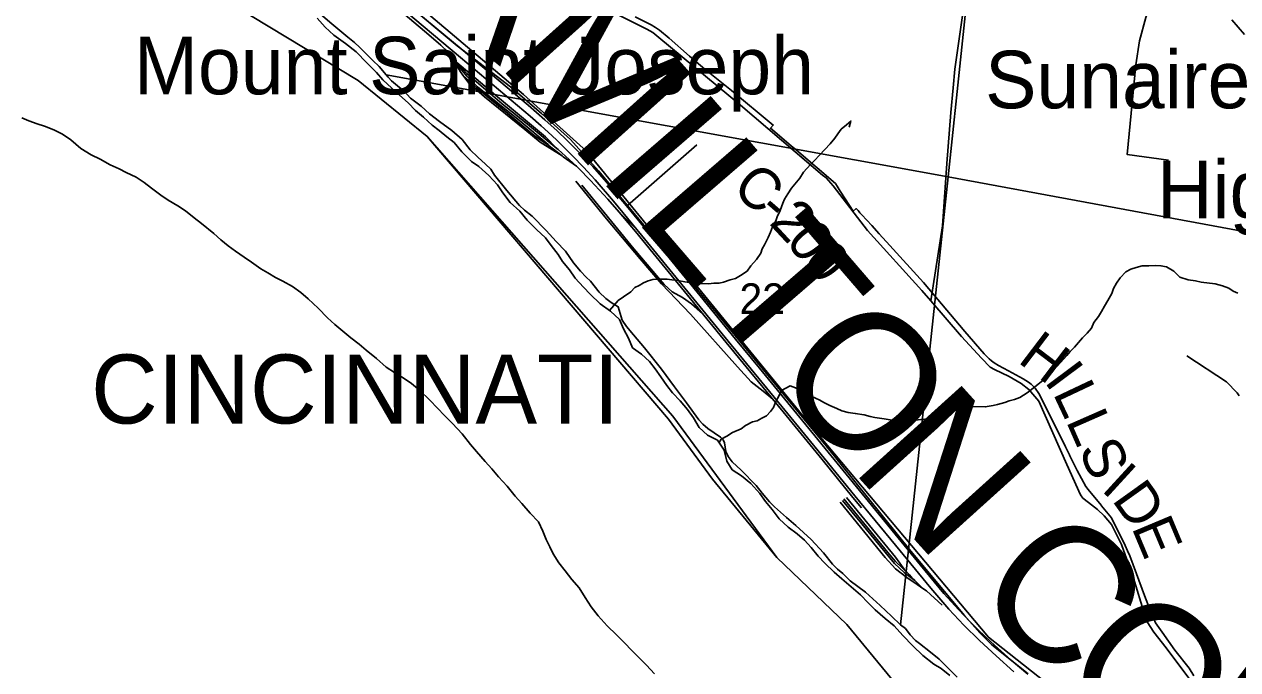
# Model space of a CAD drawing. Extents: x 0 to 43.4, y -8.1 to 22.
# Drawn here: x 5.251 to 6.917, y 14.72 to 15.605 of the extents above; entities that cross this region are included whole.
import ezdxf

# ---------------------------------------------------------------- set-up
doc = ezdxf.new("R2010")
doc.units = 0
for name, color, linetype in [('GM_X_City_Street', 7, 'Continuous'), ('GM_X_Corporation', 7, 'Continuous'), ('GM_X_Corporation_Text', 7, 'Continuous'), ('GM_X_County_Road', 7, 'Continuous'), ('GM_X_County_Road_Text', 7, 'Continuous'), ('GM_X_County_Text', 7, 'Continuous'), ('GM_X_Major_River', 7, 'Continuous'), ('GM_X_Minor_River', 7, 'Continuous'), ('GM_X_Rail_Line', 7, 'Continuous'), ('GM_X_Section_Text', 7, 'Continuous'), ('GM_X_Township_Road', 7, 'Continuous'), ('GM_X_Unincorporated_Text', 7, 'Continuous'), ('GM_X_US_Route', 7, 'Continuous')]:
    doc.layers.add(name, color=color, linetype=linetype)

msp = doc.modelspace()

# ---------------------------------------------------------------- linework, layer by layer
at = {"layer": 'GM_X_City_Street'}
msp.add_line((6.0794, 15.3567), (6.1746, 15.4398), dxfattribs=at)
at = {"layer": 'GM_X_Corporation'}
for points in [[(6.6267, 16.4119), (6.5194, 15.3962), (5.7481, 15.5362), (5.7385, 15.5474), (5.73, 15.5559), (5.7193, 15.566), (5.7119, 15.5734), (5.7045, 15.5804), (5.6956, 15.5878), (5.6844, 15.5968), (5.6733, 15.6058), (5.6644, 15.6136), (5.6543, 15.6226), (5.6473, 15.6288), (5.6384, 15.6362), (5.6358, 15.6382), (5.7092, 16.4607)], [(7.6501, 16.228), (7.5438, 15.2065), (6.5194, 15.3962), (6.6267, 16.4119)], [(6.5194, 15.3962), (6.4541, 14.7814), (6.4415, 14.7931), (6.426, 14.8079), (6.4059, 14.8262), (6.3851, 14.8418), (6.3751, 14.8519), (6.3677, 14.8578), (6.3607, 14.8644), (6.3482, 14.8802), (6.3316, 14.8984), (6.3104, 14.9175), (6.2974, 14.9284), (6.2811, 14.9432), (6.2741, 14.9502), (6.2641, 14.9618), (6.2561, 14.9726), (6.2354, 14.9936), (6.2231, 15.0049), (6.2176, 15.0122), (6.2144, 15.0191), (6.2124, 15.0309), (6.2106, 15.0351), (6.2069, 15.0386), (6.1894, 15.0508), (6.1827, 15.0566), (6.1772, 15.0624), (6.1603, 15.086), (6.1438, 15.108), (6.1258, 15.1319), (6.1027, 15.1612), (6.0876, 15.1794), (6.078, 15.1906), (6.0722, 15.1995), (6.0665, 15.2178), (6.0568, 15.2237), (6.0498, 15.2292), (6.0405, 15.2377), (6.0284, 15.2528), (6.0224, 15.2583), (6.0147, 15.2664), (6.0051, 15.278), (5.9941, 15.2938), (5.9812, 15.3074), (5.9679, 15.3225), (5.9483, 15.3419), (5.9379, 15.3501), (5.9309, 15.3567), (5.9136, 15.3772), (5.897, 15.3984), (5.8916, 15.4065), (5.8845, 15.4135), (5.8738, 15.4229), (5.8634, 15.433), (5.8524, 15.4473), (5.8383, 15.4594), (5.8215, 15.4719), (5.8074, 15.4825), (5.7959, 15.493), (5.7926, 15.4957), (5.7814, 15.5039), (5.7718, 15.5144), (5.7666, 15.5187), (5.7555, 15.528), (5.7507, 15.5327), (5.7481, 15.5362)]]:
    msp.add_lwpolyline(points, close=True, dxfattribs=at)
for points in [[(4.2564, 15.9373), (4.3533, 15.9108), (4.4487, 15.8964), (4.6416, 15.8531), (4.7366, 15.8474), (5.0291, 15.858), (5.1241, 15.8235), (5.4143, 15.7071), (5.7095, 15.5281), (5.8045, 15.4515), (6.1414, 15.0677), (6.2843, 14.8736), (6.3804, 14.7818), (6.459, 14.6859)], [(4.2564, 15.9373), (4.3533, 15.9108), (4.4487, 15.8964), (4.6416, 15.8531), (4.7366, 15.8474), (5.0291, 15.858), (5.1241, 15.8235), (5.4143, 15.7071), (5.7095, 15.5281), (5.8045, 15.4515), (6.1354, 15.0635), (6.1959, 14.9813), (6.2842, 14.8736), (6.3804, 14.7818), (6.459, 14.6859)], [(4.2564, 15.9373), (4.3533, 15.9108), (4.4487, 15.8964), (4.6416, 15.8531), (4.7366, 15.8474), (5.0291, 15.858), (5.1241, 15.8235), (5.4143, 15.7071), (5.7095, 15.5281), (5.8045, 15.4515), (6.1414, 15.0677), (6.2843, 14.8736), (6.3804, 14.7818), (6.459, 14.6859)], [(6.8566, 14.7114), (6.8502, 14.7219), (6.8308, 14.7465), (6.8133, 14.7711), (6.8111, 14.7742), (6.8041, 14.784), (6.7996, 14.795), (6.7955, 14.8052), (6.7903, 14.818), (6.769, 14.876), (6.7657, 14.8828), (6.7622, 14.8899), (6.7437, 14.928), (6.7299, 14.9447), (6.7294, 14.9453), (6.7115, 14.9671), (6.7084, 14.9709), (6.6966, 14.993), (6.691, 15.0041), (6.6865, 15.0132), (6.686, 15.0143), (6.6804, 15.0253), (6.6471, 15.0929), (6.6439, 15.0989), (6.639, 15.1058), (6.6366, 15.1084), (6.6334, 15.1114), (6.6297, 15.1142), (6.6222, 15.1186), (6.6021, 15.1297), (6.5887, 15.1371), (6.5828, 15.1407), (6.5788, 15.1435), (6.5757, 15.1461), (6.5687, 15.1529), (6.5424, 15.184), (6.4856, 15.2508), (6.4394, 15.3018), (6.4246, 15.318), (6.4145, 15.3291), (6.401, 15.344), (6.3997, 15.3454), (6.3984, 15.3468), (6.3971, 15.3482), (6.3958, 15.3496), (6.3945, 15.3511), (6.3933, 15.3524), (6.389, 15.3487), (6.3722, 15.3749), (6.3715, 15.376), (6.3713, 15.3763), (6.367, 15.3831), (6.3647, 15.3867), (6.3112, 15.4324), (6.3041, 15.4384), (6.2756, 15.4628), (6.2794, 15.467), (6.222, 15.5143), (6.1857, 15.5437), (6.1644, 15.5618), (6.1363, 15.5861), (6.1234, 15.5972), (6.1177, 15.601), (6.1118, 15.6044), (6.09, 15.6155)], [(6.5319, 14.7095), (6.5179, 14.7231), (6.5071, 14.7339), (6.4952, 14.7437), (6.48, 14.7554), (6.4748, 14.7597), (6.4674, 14.7675), (6.4608, 14.776), (6.4541, 14.7814), (6.5194, 15.3962), (7.5438, 15.2065), (7.4624, 14.2166)]]:
    msp.add_lwpolyline(points, dxfattribs=at)
at = {"layer": 'GM_X_County_Road'}
for points in [[(6.5262, 15.5183), (6.5284, 15.5439), (6.5532, 15.717)], [(6.0565, 15.6232), (6.106, 15.5986), (6.1139, 15.5943), (6.1224, 15.5872), (6.2346, 15.4945), (6.347, 15.3984), (6.3522, 15.3945), (6.3615, 15.3837), (6.4087, 15.3224), (6.4835, 15.24), (6.4957, 15.2257), (6.5378, 15.177), (6.5652, 15.1472), (6.5771, 15.1348), (6.5831, 15.1316), (6.6034, 15.1221), (6.6195, 15.1122), (6.6303, 15.1044), (6.644, 15.0882), (6.6823, 15.0013), (6.7011, 14.9595), (6.7044, 14.9549), (6.7122, 14.949), (6.7245, 14.9393), (6.7334, 14.9308), (6.7438, 14.9188), (6.7576, 14.8915), (6.774, 14.8453), (6.7889, 14.7957), (6.7928, 14.7854), (6.8016, 14.7711), (6.8186, 14.7495), (6.8606, 14.6933)], [(6.4957, 15.2257), (6.5116, 15.3289), (6.5175, 15.4145), (6.5233, 15.4845), (6.5262, 15.5183)]]:
    msp.add_lwpolyline(points, dxfattribs=at)
at = {"layer": 'GM_X_Major_River'}
for points in [[(5.9843, 15.2894), (5.9747, 15.3017), (5.9669, 15.3121), (5.9545, 15.3237), (5.9418, 15.3364), (5.9314, 15.3487), (5.9183, 15.3607), (5.9083, 15.3741), (5.9009, 15.3849), (5.8889, 15.398), (5.8755, 15.4103), (5.865, 15.4169), (5.8519, 15.4304), (5.8415, 15.4431), (5.8313, 15.4509), (5.8209, 15.4598), (5.8111, 15.4668), (5.7992, 15.478), (5.7883, 15.4872), (5.7782, 15.4977), (5.7666, 15.5081), (5.7558, 15.5178), (5.7434, 15.5293), (5.7349, 15.539), (5.7214, 15.5525), (5.7069, 15.5675), (5.6923, 15.5791), (5.6761, 15.5904), (5.6645, 15.6016), (5.6533, 15.6139)], [(5.248, 15.4769), (5.2578, 15.4729), (5.2691, 15.4686), (5.2789, 15.4654), (5.2921, 15.4606), (5.3038, 15.4547), (5.3154, 15.4469), (5.3289, 15.435), (5.3431, 15.426), (5.3556, 15.4201), (5.3691, 15.4123), (5.3815, 15.4068), (5.3913, 15.4021), (5.4049, 15.3954), (5.4158, 15.3884), (5.4259, 15.3807), (5.439, 15.371), (5.4488, 15.364), (5.4623, 15.3562), (5.4728, 15.3492), (5.4844, 15.3399), (5.4945, 15.3321)], [(5.4945, 15.3321), (5.5114, 15.3182), (5.5211, 15.3097), (5.5312, 15.3015), (5.5414, 15.2942), (5.553, 15.286), (5.5631, 15.279), (5.5759, 15.2697), (5.5856, 15.2642), (5.5962, 15.258), (5.6063, 15.2529), (5.6195, 15.2455), (5.6311, 15.2373), (5.6408, 15.2284), (5.6547, 15.2157), (5.6677, 15.2026), (5.6775, 15.1933), (5.6887, 15.1844), (5.6996, 15.1751), (5.7108, 15.1662), (5.7205, 15.1581), (5.7348, 15.1465), (5.7482, 15.1349), (5.7595, 15.1275), (5.773, 15.1193), (5.7828, 15.1123), (5.794, 15.1034), (5.8082, 15.0895), (5.8187, 15.0787), (5.828, 15.0687), (5.8392, 15.0575), (5.8523, 15.0433), (5.8638, 15.0287), (5.872, 15.019), (5.8839, 15.0052), (5.8932, 14.9952), (5.9022, 14.9844), (5.9141, 14.9717), (5.9253, 14.9578), (5.9342, 14.9478), (5.9458, 14.9347), (5.957, 14.9228), (5.9632, 14.9098), (5.9676, 14.8983), (5.9727, 14.8884), (5.9771, 14.8788), (5.9853, 14.8662), (5.9938, 14.8554), (6.0031, 14.8435), (6.0132, 14.832), (6.021, 14.8189), (6.0295, 14.8059), (6.0391, 14.7936), (6.0514, 14.7797), (6.0642, 14.7674), (6.0757, 14.7562), (6.0847, 14.7466), (6.0948, 14.7365), (6.1056, 14.7261), (6.1164, 14.7138)], [(6.5219, 14.7115), (6.5099, 14.7212), (6.4998, 14.7274), (6.4848, 14.7391), (6.4709, 14.7522), (6.4571, 14.7668), (6.4452, 14.7799), (6.4328, 14.79), (6.4194, 14.802), (6.4097, 14.8112), (6.3992, 14.8224), (6.3865, 14.8332), (6.3734, 14.8444), (6.3629, 14.8533), (6.3502, 14.8657), (6.3412, 14.8753), (6.3312, 14.8872), (6.3222, 14.8976), (6.3121, 14.9061), (6.2998, 14.9151), (6.2874, 14.9266), (6.2781, 14.9397), (6.2688, 14.9505), (6.261, 14.9616), (6.2487, 14.9751), (6.2356, 14.9859), (6.2229, 14.9941), (6.2155, 15.006), (6.2119, 15.0208), (6.203, 15.0346), (6.1891, 15.0417), (6.1779, 15.0521), (6.1701, 15.0655), (6.1619, 15.0767), (6.1515, 15.0886), (6.1411, 15.0998), (6.1333, 15.1098), (6.1251, 15.1217), (6.1173, 15.1324), (6.1095, 15.1428), (6.0987, 15.1528), (6.0863, 15.1614), (6.0808, 15.1744), (6.0738, 15.1874), (6.0683, 15.2004), (6.056, 15.2116), (6.0417, 15.2217), (6.0283, 15.2352), (6.0189, 15.2448), (6.0077, 15.2571), (5.9999, 15.2683), (5.9903, 15.2798), (5.9843, 15.2894)]]:
    msp.add_lwpolyline(points, dxfattribs=at)
at = {"layer": 'GM_X_Minor_River'}
for points in [[(6.9089, 15.6114), (6.926, 15.5915)], [(6.0548, 15.2124), (6.0667, 15.2262), (6.0737, 15.2314), (6.0837, 15.238), (6.0892, 15.244), (6.0953, 15.2469), (6.1011, 15.2506), (6.1077, 15.2532), (6.1142, 15.255), (6.1207, 15.2556), (6.1337, 15.2554), (6.1402, 15.2545), (6.1482, 15.2536), (6.1581, 15.2519), (6.1676, 15.2506), (6.1764, 15.2497), (6.1905, 15.2494), (6.1977, 15.25), (6.205, 15.2503), (6.2111, 15.2517), (6.2204, 15.2546), (6.2277, 15.2567), (6.2346, 15.2604), (6.2435, 15.2667), (6.2486, 15.2738), (6.2564, 15.2824), (6.2623, 15.2915), (6.2643, 15.2971), (6.2674, 15.3028), (6.2722, 15.313), (6.2754, 15.3201), (6.2782, 15.3273), (6.2829, 15.3356), (6.2849, 15.3412), (6.2889, 15.3499), (6.2925, 15.3597), (6.2949, 15.3654), (6.2993, 15.3725), (6.3044, 15.3804), (6.3157, 15.3943), (6.3208, 15.4025), (6.3306, 15.413), (6.336, 15.4186), (6.343, 15.4257), (6.35, 15.4336), (6.3574, 15.4414), (6.3637, 15.4493), (6.368, 15.4549), (6.3727, 15.4613), (6.3797, 15.4673), (6.3859, 15.4725), (6.3838, 15.4641)], [(6.2051, 15.0313), (6.208, 15.0359), (6.2157, 15.0403), (6.2234, 15.0451), (6.2353, 15.0502), (6.2415, 15.055), (6.2508, 15.0598), (6.2573, 15.0612), (6.2635, 15.0649), (6.27, 15.0682), (6.2755, 15.0738), (6.2798, 15.0794), (6.2826, 15.0866), (6.2874, 15.096), (6.2905, 15.1028), (6.3025, 15.1091), (6.3101, 15.1063), (6.3191, 15.1015), (6.3248, 15.0984), (6.3316, 15.0949), (6.3434, 15.0897), (6.349, 15.0862), (6.357, 15.0822), (6.3665, 15.0783), (6.3733, 15.0747), (6.382, 15.0727), (6.3919, 15.0713), (6.4041, 15.0692), (6.4125, 15.0672), (6.4189, 15.0659), (6.4254, 15.0647), (6.4315, 15.0638), (6.4372, 15.0629), (6.4456, 15.0616), (6.4536, 15.0604), (6.4616, 15.0602), (6.4677, 15.0605), (6.4746, 15.0619), (6.4819, 15.0629), (6.4876, 15.0636), (6.4945, 15.0646), (6.501, 15.0648), (6.5072, 15.0662), (6.516, 15.068), (6.5229, 15.0724), (6.531, 15.0765), (6.5379, 15.0798), (6.5452, 15.0804), (6.5517, 15.0807), (6.5704, 15.0803), (6.5811, 15.0824), (6.5873, 15.0838), (6.5973, 15.0863), (6.603, 15.0885), (6.6107, 15.0906), (6.618, 15.0932), (6.6277, 15.0994), (6.6362, 15.1058), (6.6494, 15.1165), (6.6552, 15.1233), (6.6637, 15.1303), (6.6739, 15.1416), (6.6824, 15.1509), (6.6867, 15.1565), (6.693, 15.1621), (6.7039, 15.1752), (6.7101, 15.1816), (6.716, 15.1883), (6.7195, 15.1962), (6.7258, 15.2045), (6.7301, 15.2113), (6.7341, 15.2184), (6.7384, 15.2263), (6.7439, 15.2357), (6.7464, 15.2429), (6.7503, 15.2501), (6.7554, 15.2572), (6.7632, 15.2658), (6.7701, 15.2691), (6.7774, 15.2716), (6.7859, 15.2737), (6.795, 15.274), (6.8046, 15.2745), (6.8115, 15.274), (6.8191, 15.2724), (6.8293, 15.2665), (6.8375, 15.2584), (6.8489, 15.2547), (6.8588, 15.2531), (6.8668, 15.2514), (6.8859, 15.2491), (6.8961, 15.2463), (6.9045, 15.2431), (6.9105, 15.2392), (6.9169, 15.2364)]]:
    msp.add_lwpolyline(points, dxfattribs=at)
at = {"layer": 'GM_X_Rail_Line'}
for p, q in [((5.8404, 15.5567), (5.8328, 15.5675)), ((5.9895, 15.4248), (5.972, 15.4388)), ((6.4737, 14.8419), (6.4847, 14.8311))]:
    msp.add_line(p, q, dxfattribs=at)
for points in [[(4.1978, 16.2749), (4.2934, 16.2188), (4.3976, 16.1704), (4.4935, 16.127), (4.6314, 16.1011), (4.6907, 16.0865), (4.93, 15.9917), (5.1919, 15.9535), (5.3649, 15.9245), (5.4749, 15.8856), (5.5993, 15.8084), (5.7206, 15.6918), (5.9364, 15.5089), (6.0231, 15.4314), (6.3347, 15.0503), (6.5747, 14.7641), (6.7584, 14.6191)], [(5.8328, 15.5675), (5.823, 15.5766), (5.8067, 15.5911), (5.7535, 15.6359), (5.7303, 15.6602)], [(5.7557, 15.651), (5.8511, 15.5715), (5.943, 15.4944), (5.966, 15.4741), (5.9828, 15.459), (5.9963, 15.4461), (6.0138, 15.4285), (6.0316, 15.41), (6.0506, 15.3886), (6.078, 15.3562), (6.1264, 15.2972), (6.2276, 15.1734), (6.2604, 15.1335), (6.3755, 14.9928), (6.4815, 14.8629), (6.5134, 14.8244), (6.5336, 14.8022), (6.549, 14.7858), (6.5612, 14.7737), (6.5779, 14.7577), (6.5921, 14.7449), (6.606, 14.7326), (6.6287, 14.7137)], [(5.7619, 15.634), (5.8503, 15.5596), (5.9458, 15.4792), (5.9608, 15.4661), (5.9704, 15.4573), (5.9817, 15.447), (5.9929, 15.4357), (6.0045, 15.4244), (6.019, 15.4091), (6.0349, 15.3917), (6.0602, 15.3627), (6.0987, 15.316), (6.2175, 15.1707), (6.2955, 15.0757), (6.3492, 15.01), (6.3914, 14.9584), (6.4474, 14.8904), (6.4959, 14.8315), (6.5203, 14.8026), (6.5411, 14.7806), (6.5624, 14.7596), (6.5852, 14.7385), (6.6098, 14.7169)], [(5.845, 15.5531), (5.8331, 15.5672), (5.8328, 15.5675)], [(5.972, 15.4388), (5.9703, 15.4402), (5.9315, 15.4728), (5.8735, 15.5195), (5.8587, 15.5341), (5.8431, 15.5528), (5.8404, 15.5567)], [(5.8404, 15.5567), (5.8502, 15.5402), (5.8535, 15.5355)], [(5.9823, 15.4348), (5.9446, 15.4659), (5.9071, 15.4963), (5.8591, 15.5373), (5.8469, 15.5508), (5.845, 15.5531)], [(5.845, 15.5531), (5.8983, 15.508), (5.9667, 15.451), (5.9823, 15.4348)], [(5.972, 15.4388), (5.9512, 15.4527), (5.9123, 15.4854), (5.8718, 15.5185), (5.8535, 15.5355)], [(5.8535, 15.5355), (5.8614, 15.5245), (5.8829, 15.506), (5.9385, 15.4609), (5.9596, 15.4434), (5.9895, 15.4248)], [(6.0092, 15.4106), (5.9841, 15.4334), (5.9823, 15.4348)], [(6.0092, 15.4106), (5.9911, 15.4235), (5.9895, 15.4248)], [(6.0678, 15.3477), (6.0522, 15.3654), (6.0287, 15.391), (6.0122, 15.4079), (6.0092, 15.4106)], [(6.2786, 15.091), (6.2654, 15.1021), (6.2492, 15.1147), (6.2302, 15.1352), (6.1659, 15.2075), (6.1261, 15.2494), (6.0965, 15.2836), (6.0507, 15.3384), (6.0086, 15.3903)], [(6.0165, 15.3846), (6.0881, 15.2974), (6.1298, 15.2482), (6.1407, 15.2383), (6.155, 15.2304), (6.1672, 15.2217), (6.1824, 15.2083)], [(6.0931, 15.3228), (6.0693, 15.346), (6.0678, 15.3477)], [(6.0678, 15.3477), (6.0925, 15.3183), (6.0961, 15.3139), (6.2149, 15.1686), (6.2929, 15.0735), (6.3466, 15.0079), (6.3888, 14.9562), (6.4006, 14.9419)], [(6.4847, 14.8311), (6.4768, 14.8365), (6.4626, 14.846), (6.4472, 14.8579), (6.4328, 14.8736), (6.3712, 14.9494)], [(6.4737, 14.8419), (6.4589, 14.8529), (6.4458, 14.8654), (6.4009, 14.9199), (6.3743, 14.9519)], [(6.3764, 14.9541), (6.4367, 14.8803), (6.447, 14.8683), (6.4664, 14.8497)], [(6.3798, 14.9561), (6.447, 14.8739), (6.4593, 14.8577), (6.4664, 14.8497)], [(6.4664, 14.8497), (6.4702, 14.8453), (6.4737, 14.8419)], [(6.5112, 14.8082), (6.4897, 14.8277), (6.4847, 14.8311)]]:
    msp.add_lwpolyline(points, dxfattribs=at)
at = {"layer": 'GM_X_Township_Road'}
for points in [[(6.8221, 15.4189), (6.765, 15.4268), (6.7772, 15.5499), (6.7823, 15.5827), (6.7908, 15.6145), (6.802, 15.6482)], [(6.8471, 15.1505), (6.9013, 15.1146), (6.9163, 15.0994), (6.9189, 15.0956)]]:
    msp.add_lwpolyline(points, dxfattribs=at)
at = {"layer": 'GM_X_US_Route'}
msp.add_lwpolyline([(5.6607, 15.7259), (5.6849, 15.7062), (5.7001, 15.6938), (5.7736, 15.6358), (5.8456, 15.5756), (5.9188, 15.5196), (5.9615, 15.4831), (6.0011, 15.4471), (6.0397, 15.4044), (6.0794, 15.3567), (6.1454, 15.2774), (6.3518, 15.027), (6.4684, 14.8825), (6.5421, 14.7941), (6.563, 14.7704), (6.5793, 14.7537), (6.6291, 14.7139)], dxfattribs=at)

# ---------------------------------------------------------------- texts
at = {"layer": 'GM_X_Corporation_Text'}
msp.add_text('CINCINNATI', height=0.0947, rotation=0, dxfattribs=at).set_placement((5.3431, 15.0575))
at = {"layer": 'GM_X_County_Road_Text'}
for s, rotation, p in [('C', 319.2139, (6.2207, 15.3771)), ('-', 319.0935, (6.256, 15.3466)), ('2', 312.9177, (6.2725, 15.3325)), ('0', 307.5152, (6.2954, 15.3079)), ('0', 309.2083, (6.3178, 15.2787)), ('H', 322.7635, (6.6135, 15.1426)), ('I', 306.7122, (6.6503, 15.1154)), ('L', 295.2837, (6.6627, 15.0992)), ('L', 293.7034, (6.6807, 15.0612)), ('S', 293.5899, (6.6978, 15.0223)), ('I', 317.5313, (6.7281, 14.9662)), ('D', 305.5868, (6.7432, 14.9528)), ('E', 292.7395, (6.7707, 14.9151))]:
    msp.add_text(s, height=0.0568, rotation=rotation, dxfattribs=at).set_placement(p)
at = {"layer": 'GM_X_County_Text'}
for s, rotation, p in [('A', 320.9905, (5.7737, 15.6534)), ('M', 311.8731, (5.8981, 15.5534)), ('I', 310.852, (6.0349, 15.4008)), ('L', 310.7782, (6.0855, 15.3423)), ('T', 310.7744, (6.1781, 15.235)), ('O', 310.9226, (6.2709, 15.1273)), ('N', 312.0598, (6.3834, 14.9977)), ('C', 315.9774, (6.5454, 14.8218)), ('O', 318.4967, (6.6629, 14.7085)), ('U', 322.8562, (6.8005, 14.5875))]:
    msp.add_text(s, height=0.1894, rotation=rotation, dxfattribs=at).set_placement(p)
at = {"layer": 'GM_X_Section_Text'}
msp.add_text('22', height=0.04186, rotation=0, dxfattribs=at).set_placement((6.2331, 15.208))
at = {"layer": 'GM_X_Unincorporated_Text'}
for s, height, p in [('Mount Saint Joseph', 0.078977, (5.4018, 15.5093)), ('Sunaire', 0.07898, (6.5702, 15.4901)), ('Highland Park', 0.078977, (6.806, 15.3393))]:
    msp.add_text(s, height=height, rotation=0, dxfattribs=at).set_placement(p)

doc.saveas('drawing.dxf')
